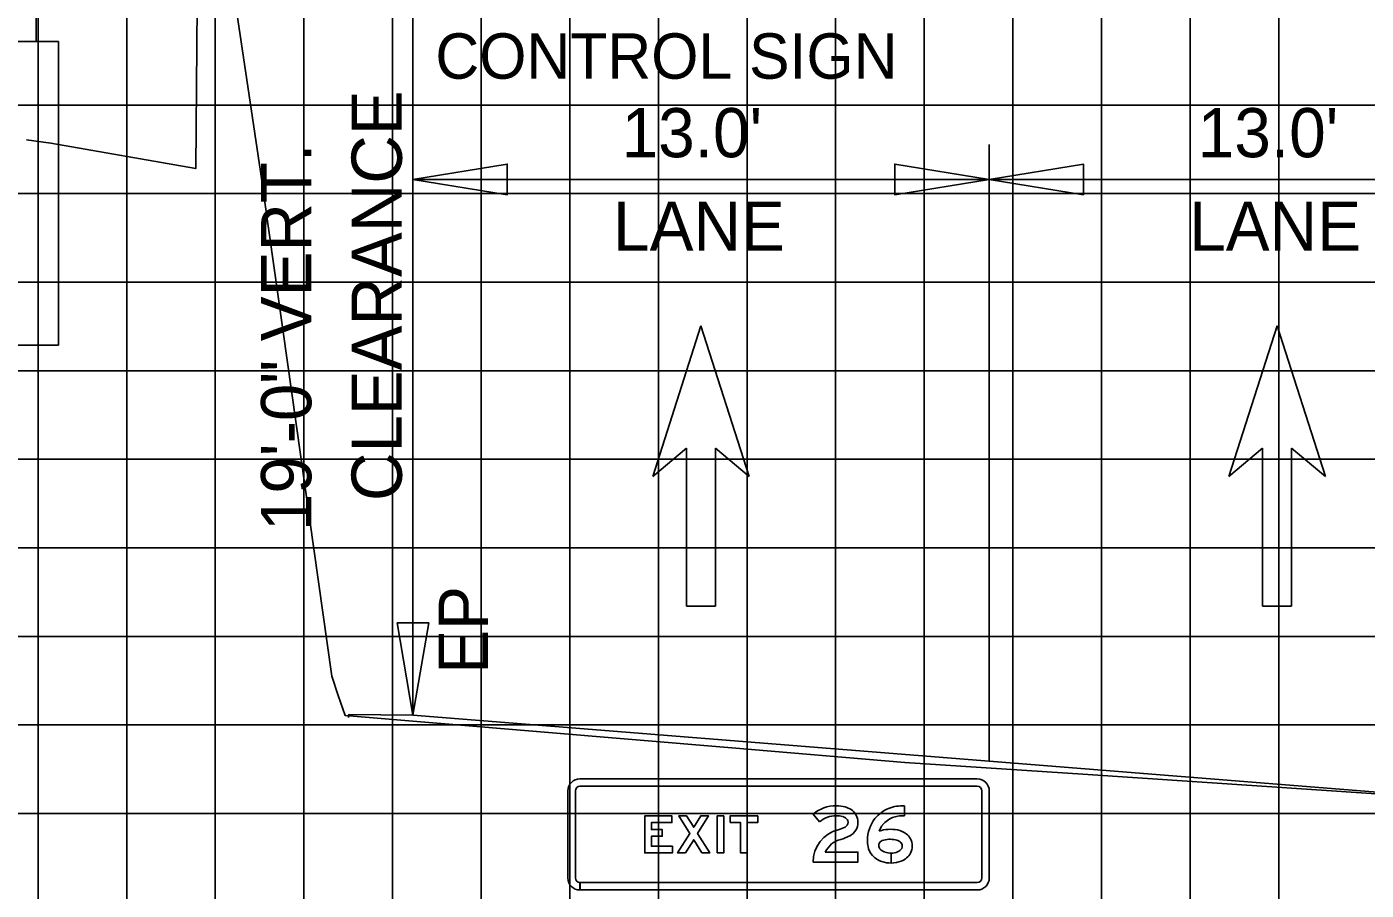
# Model space of a CAD drawing. Extents: x 2193008 to 2198143, y 1236112 to 1237864.
# Drawn here: x 2195346.38 to 2195376.61, y 1237268.37 to 1237287.87 of the extents above; entities that cross this region are included whole.
import ezdxf

# ---------------------------------------------------------------- set-up
doc = ezdxf.new("R2010")
doc.units = 0
for name, color, linetype in [('3', 7, 'Continuous'), ('CL-CNST', 7, 'Continuous'), ('GSBWFILL', 7, 'Continuous'), ('GSCOLORFILL', 7, 'Continuous'), ('GSDIMS', 7, 'Continuous'), ('GSOUTLINE', 7, 'Continuous'), ('Level 28', 7, 'Continuous'), ('Level 55', 7, 'Continuous'), ('Level 62', 7, 'Continuous'), ('M-ROADS', 7, 'Continuous'), ('V7Level1', 7, 'Continuous')]:
    doc.layers.add(name, color=color, linetype=linetype)

msp = doc.modelspace()

# ---------------------------------------------------------------- linework, layer by layer
at = {"layer": '3'}
for p, q in [((2195346.592, 1237301.295), (2195346.592, 1237287.538)), ((2195355.092, 1237272.327), (2195355.092, 1237291.42)), ((2195345.092, 1237287.538), (2195347.092, 1237287.538)), ((2195347.092, 1237280.686), (2195347.092, 1237287.538)), ((2195368.094, 1237271.287), (2195368.094, 1237285.215)), ((2195345.092, 1237280.686), (2195347.092, 1237280.686))]:
    msp.add_line(p, q, dxfattribs=at)
at = {"layer": 'CL-CNST'}
msp.add_lwpolyline([(2195353.64, 1237272.272), (2195353.643, 1237272.341), (2195355.092, 1237272.327), (2195368.094, 1237271.287), (2195381.096, 1237270.247), (2195387.382, 1237269.744)], dxfattribs=at)
at = {"layer": 'GSBWFILL'}
for points in [[(2195366.185, 1237270.282), (2195366.185, 1237270.057)], [(2195364.269, 1237269.918), (2195364.123, 1237270.09)], [(2195364.399, 1237269.235), (2195365.136, 1237269.235), (2195365.136, 1237269.01), (2195364.123, 1237269.01)], [(2195365.888, 1237269.213), (2195365.888, 1237268.988)], [(2195365.888, 1237268.988), (2195365.888, 1237269.213)]]:
    msp.add_lwpolyline(points, dxfattribs=at)
for points in [[(2195360.948, 1237269.368), (2195360.473, 1237269.368), (2195360.473, 1237269.592), (2195360.719, 1237269.592), (2195360.719, 1237269.742), (2195360.473, 1237269.742), (2195360.473, 1237269.901), (2195360.936, 1237269.901), (2195360.936, 1237270.051), (2195360.323, 1237270.051), (2195360.323, 1237269.218), (2195360.948, 1237269.218)], [(2195361.613, 1237269.218), (2195361.428, 1237269.514), (2195361.242, 1237269.218), (2195361.065, 1237269.218), (2195361.339, 1237269.655), (2195361.09, 1237270.051), (2195361.267, 1237270.051), (2195361.428, 1237269.796), (2195361.588, 1237270.051), (2195361.765, 1237270.051), (2195361.516, 1237269.655), (2195361.79, 1237269.218)], [(2195361.957, 1237269.218), (2195361.957, 1237270.051), (2195362.107, 1237270.051), (2195362.107, 1237269.218)], [(2195362.248, 1237269.901), (2195362.486, 1237269.901), (2195362.486, 1237269.218), (2195362.636, 1237269.218), (2195362.636, 1237269.901), (2195362.873, 1237269.901), (2195362.873, 1237270.051), (2195362.248, 1237270.051)]]:
    msp.add_lwpolyline(points, close=True, dxfattribs=at)
for centre, major_axis, start_param, end_param in [((2195364.645, 1237269.475), (0, 0.807), 0, 0.70376), ((2195364.645, 1237269.491), (0, 0.79), 6.02311, 6.283185), ((2195364.731, 1237269.812), (0, 0.458), 5.706931, 6.02311), ((2195366.102, 1237269.546), (0, 0.73), 0.134155, 0.638471), ((2195366.185, 1237268.93), (0, 1.352), 6.283185, 6.41734), ((2195364.645, 1237269.475), (0, 0.582), 0, 0.70376), ((2195364.645, 1237269.491), (0, 0.565), 6.02311, 6.283185), ((2195364.731, 1237269.812), (0, 0.233), 5.706931, 6.02311), ((2195364.794, 1237269.91), (0, 0.117), 4.712389, 5.706931), ((2195364.794, 1237269.91), (0, 0.342), 4.712389, 5.706931), ((2195366.146, 1237269.501), (0, 0.797), 0.905406, 1.570796), ((2195366.199, 1237269.415), (0, 0.893), 0.638464, 0.866813), ((2195366.199, 1237269.415), (0, 0.668), 0.638461, 0.860244), ((2195366.102, 1237269.546), (0, 0.505), 0.134155, 0.638471), ((2195366.185, 1237268.93), (0, 1.127), 0, 0.134155), ((2195364.878, 1237269.01), (0, 0.755), 0.25053, 1.570796), ((2195364.516, 1237270.423), (0, 0.704), 3.392123, 3.626327), ((2195364.787, 1237269.91), (0, 0.124), 3.626327, 4.712389), ((2195364.787, 1237269.91), (0, 0.349), 3.626327, 4.712389), ((2195366.146, 1237269.501), (0, 0.572), 0.912917, 1.195206), ((2195365.866, 1237268.921), (0, 0.829), 6.090019, 6.593179), ((2195365.932, 1237269.257), (0, 0.487), 5.634496, 6.090017), ((2195366.024, 1237269.378), (0, 0.335), 5.237857, 5.634492), ((2195364.878, 1237269.01), (0, 0.53), 0.25053, 1.132058), ((2195364.516, 1237270.423), (0, 0.929), 3.392123, 3.626327), ((2195366.014, 1237269.501), (0, 0.666), 1.570796, 1.784619), ((2195365.759, 1237269.431), (0, 0.402), 1.748918, 2.304124), ((2195365.723, 1237269.384), (0, 0.119), 0.35159, 2.216564), ((2195365.866, 1237268.921), (0, 0.604), 6.090019, 6.593179), ((2195365.932, 1237269.257), (0, 0.262), 5.6345, 6.090015), ((2195366.024, 1237269.378), (0, 0.11), 5.237857, 5.634492), ((2195366.009, 1237269.37), (0, 0.127), 4.712389, 5.237857), ((2195366.021, 1237269.37), (0, 0.115), 4.261086, 4.712389), ((2195366.009, 1237269.37), (0, 0.352), 4.712389, 5.237857), ((2195366.021, 1237269.37), (0, 0.34), 4.229443, 4.712389), ((2195365.831, 1237269.496), (0, 0.499), 2.304124, 2.823757), ((2195365.831, 1237269.496), (0, 0.274), 2.304124, 2.823757), ((2195365.888, 1237269.667), (0, 0.454), 2.823757, 3.141593), ((2195365.888, 1237269.603), (0, 0.39), 3.141673, 3.514879), ((2195365.888, 1237269.603), (0, 0.615), 3.141643, 3.514879), ((2195365.96, 1237269.418), (0, 0.192), 3.51487, 4.172439), ((2195365.96, 1237269.418), (0, 0.417), 3.514875, 4.194509), ((2195365.888, 1237269.667), (0, 0.679), 2.823757, 3.141593)]:
    msp.add_ellipse(centre, major_axis=major_axis, ratio=0.999994, start_param=start_param, end_param=end_param, dxfattribs=at)
at = {"layer": 'GSCOLORFILL'}
for p, q in [((2195367.828, 1237270.889), (2195358.861, 1237270.889)), ((2195358.59, 1237270.618), (2195358.59, 1237268.651)), ((2195358.757, 1237268.651), (2195358.757, 1237270.618)), ((2195358.861, 1237270.722), (2195367.828, 1237270.722)), ((2195367.932, 1237270.618), (2195367.932, 1237268.651)), ((2195368.098, 1237268.651), (2195368.098, 1237270.618)), ((2195358.861, 1237268.381), (2195358.861, 1237268.547)), ((2195367.828, 1237268.547), (2195358.863, 1237268.547)), ((2195358.863, 1237268.547), (2195358.863, 1237268.381)), ((2195358.863, 1237268.381), (2195367.828, 1237268.381))]:
    msp.add_line(p, q, dxfattribs=at)
for points in [[(2195366.185, 1237270.282), (2195366.185, 1237270.057)], [(2195364.269, 1237269.918), (2195364.123, 1237270.09)], [(2195364.399, 1237269.235), (2195365.136, 1237269.235), (2195365.136, 1237269.01), (2195364.123, 1237269.01)], [(2195365.888, 1237269.213), (2195365.888, 1237268.988)], [(2195365.888, 1237268.988), (2195365.888, 1237269.213)]]:
    msp.add_lwpolyline(points, dxfattribs=at)
for points in [[(2195360.948, 1237269.368), (2195360.473, 1237269.368), (2195360.473, 1237269.592), (2195360.719, 1237269.592), (2195360.719, 1237269.742), (2195360.473, 1237269.742), (2195360.473, 1237269.901), (2195360.936, 1237269.901), (2195360.936, 1237270.051), (2195360.323, 1237270.051), (2195360.323, 1237269.218), (2195360.948, 1237269.218)], [(2195361.613, 1237269.218), (2195361.428, 1237269.514), (2195361.242, 1237269.218), (2195361.065, 1237269.218), (2195361.339, 1237269.655), (2195361.09, 1237270.051), (2195361.267, 1237270.051), (2195361.428, 1237269.796), (2195361.588, 1237270.051), (2195361.765, 1237270.051), (2195361.516, 1237269.655), (2195361.79, 1237269.218)], [(2195361.957, 1237269.218), (2195361.957, 1237270.051), (2195362.107, 1237270.051), (2195362.107, 1237269.218)], [(2195362.248, 1237269.901), (2195362.486, 1237269.901), (2195362.486, 1237269.218), (2195362.636, 1237269.218), (2195362.636, 1237269.901), (2195362.873, 1237269.901), (2195362.873, 1237270.051), (2195362.248, 1237270.051)]]:
    msp.add_lwpolyline(points, close=True, dxfattribs=at)
for centre, radius, start, end in [((2195358.861, 1237270.618), 0.271, 90, 180), ((2195367.828, 1237270.618), 0.271, 0, 90), ((2195358.861, 1237270.618), 0.104, 90, 180), ((2195367.828, 1237270.618), 0.104, 0, 90), ((2195358.861, 1237268.651), 0.271, 180, 270), ((2195358.861, 1237268.651), 0.104, 180, 270), ((2195367.828, 1237268.651), 0.271, 270, 0), ((2195367.828, 1237268.651), 0.104, 270, 0)]:
    msp.add_arc(centre, radius, start, end, dxfattribs=at)
for centre, major_axis, start_param, end_param in [((2195364.645, 1237269.475), (0, 0.807), 0, 0.70376), ((2195364.645, 1237269.491), (0, 0.79), 6.02311, 6.283185), ((2195364.731, 1237269.812), (0, 0.458), 5.706931, 6.02311), ((2195366.102, 1237269.546), (0, 0.73), 0.134155, 0.638471), ((2195366.185, 1237268.93), (0, 1.352), 6.283185, 6.41734), ((2195364.645, 1237269.475), (0, 0.582), 0, 0.70376), ((2195364.645, 1237269.491), (0, 0.565), 6.02311, 6.283185), ((2195364.731, 1237269.812), (0, 0.233), 5.706931, 6.02311), ((2195364.794, 1237269.91), (0, 0.117), 4.712389, 5.706931), ((2195364.794, 1237269.91), (0, 0.342), 4.712389, 5.706931), ((2195366.146, 1237269.501), (0, 0.797), 0.905406, 1.570796), ((2195366.199, 1237269.415), (0, 0.893), 0.638464, 0.866813), ((2195366.199, 1237269.415), (0, 0.668), 0.638461, 0.860244), ((2195366.102, 1237269.546), (0, 0.505), 0.134155, 0.638471), ((2195366.185, 1237268.93), (0, 1.127), 0, 0.134155), ((2195364.878, 1237269.01), (0, 0.755), 0.25053, 1.570796), ((2195364.516, 1237270.423), (0, 0.704), 3.392123, 3.626327), ((2195364.787, 1237269.91), (0, 0.124), 3.626327, 4.712389), ((2195364.787, 1237269.91), (0, 0.349), 3.626327, 4.712389), ((2195366.146, 1237269.501), (0, 0.572), 0.912917, 1.195206), ((2195365.866, 1237268.921), (0, 0.829), 6.090019, 6.593179), ((2195365.932, 1237269.257), (0, 0.487), 5.634496, 6.090017), ((2195366.024, 1237269.378), (0, 0.335), 5.237857, 5.634492), ((2195364.878, 1237269.01), (0, 0.53), 0.25053, 1.132058), ((2195364.516, 1237270.423), (0, 0.929), 3.392123, 3.626327), ((2195366.014, 1237269.501), (0, 0.666), 1.570796, 1.784619), ((2195365.759, 1237269.431), (0, 0.402), 1.748918, 2.304124), ((2195365.723, 1237269.384), (0, 0.119), 0.35159, 2.216564), ((2195365.866, 1237268.921), (0, 0.604), 6.090019, 6.593179), ((2195365.932, 1237269.257), (0, 0.262), 5.6345, 6.090015), ((2195366.024, 1237269.378), (0, 0.11), 5.237857, 5.634492), ((2195366.009, 1237269.37), (0, 0.127), 4.712389, 5.237857), ((2195366.021, 1237269.37), (0, 0.115), 4.261086, 4.712389), ((2195366.009, 1237269.37), (0, 0.352), 4.712389, 5.237857), ((2195366.021, 1237269.37), (0, 0.34), 4.229443, 4.712389), ((2195365.831, 1237269.496), (0, 0.499), 2.304124, 2.823757), ((2195365.831, 1237269.496), (0, 0.274), 2.304124, 2.823757), ((2195365.888, 1237269.667), (0, 0.454), 2.823757, 3.141593), ((2195365.888, 1237269.603), (0, 0.39), 3.141673, 3.514879), ((2195365.888, 1237269.603), (0, 0.615), 3.141643, 3.514879), ((2195365.96, 1237269.418), (0, 0.192), 3.51487, 4.172439), ((2195365.96, 1237269.418), (0, 0.417), 3.514875, 4.194509), ((2195365.888, 1237269.667), (0, 0.679), 2.823757, 3.141593)]:
    msp.add_ellipse(centre, major_axis=major_axis, ratio=0.999994, start_param=start_param, end_param=end_param, dxfattribs=at)
at = {"layer": 'GSDIMS'}
for p, q in [((2195355.092, 1237284.427), (2195368.094, 1237284.427)), ((2195368.094, 1237284.427), (2195381.097, 1237284.427))]:
    msp.add_line(p, q, dxfattribs=at)
for points in [[(2195355.092, 1237284.427), (2195357.22, 1237284.079), (2195357.22, 1237284.774)], [(2195368.094, 1237284.427), (2195365.966, 1237284.079), (2195365.966, 1237284.774)], [(2195368.094, 1237284.427), (2195370.223, 1237284.079), (2195370.223, 1237284.774)], [(2195355.092, 1237272.327), (2195354.737, 1237274.41), (2195355.447, 1237274.41)]]:
    msp.add_lwpolyline(points, close=True, dxfattribs=at)
at = {"layer": 'GSOUTLINE'}
for points in [[(2195366.185, 1237270.282), (2195366.185, 1237270.057)], [(2195364.269, 1237269.918), (2195364.123, 1237270.09)], [(2195364.399, 1237269.235), (2195365.136, 1237269.235), (2195365.136, 1237269.01), (2195364.123, 1237269.01)]]:
    msp.add_lwpolyline(points, dxfattribs=at)
for points in [[(2195360.948, 1237269.368), (2195360.473, 1237269.368), (2195360.473, 1237269.592), (2195360.719, 1237269.592), (2195360.719, 1237269.742), (2195360.473, 1237269.742), (2195360.473, 1237269.901), (2195360.936, 1237269.901), (2195360.936, 1237270.051), (2195360.323, 1237270.051), (2195360.323, 1237269.218), (2195360.948, 1237269.218)], [(2195361.613, 1237269.218), (2195361.428, 1237269.514), (2195361.242, 1237269.218), (2195361.065, 1237269.218), (2195361.339, 1237269.655), (2195361.09, 1237270.051), (2195361.267, 1237270.051), (2195361.428, 1237269.796), (2195361.588, 1237270.051), (2195361.765, 1237270.051), (2195361.516, 1237269.655), (2195361.79, 1237269.218)], [(2195361.957, 1237269.218), (2195361.957, 1237270.051), (2195362.107, 1237270.051), (2195362.107, 1237269.218)], [(2195362.248, 1237269.901), (2195362.486, 1237269.901), (2195362.486, 1237269.218), (2195362.636, 1237269.218), (2195362.636, 1237269.901), (2195362.873, 1237269.901), (2195362.873, 1237270.051), (2195362.248, 1237270.051)]]:
    msp.add_lwpolyline(points, close=True, dxfattribs=at)
for centre, major_axis, start_param, end_param in [((2195364.645, 1237269.475), (0, 0.807), 0, 0.70376), ((2195364.645, 1237269.491), (0, 0.79), 6.02311, 6.283185), ((2195364.731, 1237269.812), (0, 0.458), 5.706931, 6.02311), ((2195366.102, 1237269.546), (0, 0.73), 0.134155, 0.638471), ((2195366.185, 1237268.93), (0, 1.352), 6.283185, 6.41734), ((2195364.645, 1237269.475), (0, 0.582), 0, 0.70376), ((2195364.645, 1237269.491), (0, 0.565), 6.02311, 6.283185), ((2195364.731, 1237269.812), (0, 0.233), 5.706931, 6.02311), ((2195364.794, 1237269.91), (0, 0.117), 4.712389, 5.706931), ((2195364.794, 1237269.91), (0, 0.342), 4.712389, 5.706931), ((2195366.146, 1237269.501), (0, 0.797), 0.905406, 1.570796), ((2195366.199, 1237269.415), (0, 0.893), 0.638464, 0.866813), ((2195366.199, 1237269.415), (0, 0.668), 0.638461, 0.860244), ((2195366.102, 1237269.546), (0, 0.505), 0.134155, 0.638471), ((2195366.185, 1237268.93), (0, 1.127), 0, 0.134155), ((2195364.878, 1237269.01), (0, 0.755), 0.25053, 1.570796), ((2195364.516, 1237270.423), (0, 0.704), 3.392123, 3.626327), ((2195364.787, 1237269.91), (0, 0.124), 3.626327, 4.712389), ((2195364.787, 1237269.91), (0, 0.349), 3.626327, 4.712389), ((2195366.146, 1237269.501), (0, 0.572), 0.912917, 1.195206), ((2195365.866, 1237268.921), (0, 0.829), 6.090019, 6.593179), ((2195365.932, 1237269.257), (0, 0.487), 5.634496, 6.090017), ((2195366.024, 1237269.378), (0, 0.335), 5.237857, 5.634492), ((2195364.878, 1237269.01), (0, 0.53), 0.25053, 1.132058), ((2195364.516, 1237270.423), (0, 0.929), 3.392123, 3.626327), ((2195366.014, 1237269.501), (0, 0.666), 1.570796, 1.784619), ((2195365.759, 1237269.431), (0, 0.402), 1.748918, 2.304124), ((2195365.723, 1237269.384), (0, 0.119), 0.35159, 2.216564), ((2195365.866, 1237268.921), (0, 0.604), 6.090019, 6.593179), ((2195365.932, 1237269.257), (0, 0.262), 5.6345, 6.090015), ((2195366.024, 1237269.378), (0, 0.11), 5.237857, 5.634492), ((2195366.009, 1237269.37), (0, 0.127), 4.712389, 5.237857), ((2195366.021, 1237269.37), (0, 0.115), 4.261086, 4.712389), ((2195366.009, 1237269.37), (0, 0.352), 4.712389, 5.237857), ((2195366.021, 1237269.37), (0, 0.34), 4.229443, 4.712389), ((2195365.831, 1237269.496), (0, 0.499), 2.304124, 2.823757), ((2195365.831, 1237269.496), (0, 0.274), 2.304124, 2.823757), ((2195365.888, 1237269.667), (0, 0.454), 2.823757, 3.141593), ((2195365.888, 1237269.603), (0, 0.39), 3.141593, 3.514879), ((2195365.888, 1237269.603), (0, 0.615), 3.141593, 3.514879), ((2195365.96, 1237269.418), (0, 0.192), 3.51487, 4.172439), ((2195365.96, 1237269.418), (0, 0.417), 3.514875, 4.194509), ((2195365.888, 1237269.667), (0, 0.679), 2.823757, 3.141593)]:
    msp.add_ellipse(centre, major_axis=major_axis, ratio=0.999994, start_param=start_param, end_param=end_param, dxfattribs=at)
at = {"layer": 'Level 28'}
for p, q in [((2195361.593, 1237281.117), (2195360.504, 1237277.719)), ((2195362.682, 1237277.719), (2195361.593, 1237281.117)), ((2195374.595, 1237281.117), (2195373.506, 1237277.719)), ((2195375.685, 1237277.719), (2195374.595, 1237281.117)), ((2195360.504, 1237277.719), (2195361.266, 1237278.359)), ((2195361.266, 1237278.359), (2195361.266, 1237274.787)), ((2195361.92, 1237274.787), (2195361.92, 1237278.359)), ((2195361.92, 1237278.359), (2195362.682, 1237277.719)), ((2195373.506, 1237277.719), (2195374.269, 1237278.359)), ((2195374.269, 1237278.359), (2195374.269, 1237274.787)), ((2195374.922, 1237274.787), (2195374.922, 1237278.359)), ((2195374.922, 1237278.359), (2195375.685, 1237277.719)), ((2195361.266, 1237274.787), (2195361.92, 1237274.787)), ((2195374.269, 1237274.787), (2195374.922, 1237274.787))]:
    msp.add_line(p, q, dxfattribs=at)
at = {"layer": 'Level 62'}
for p, q in [((2195346.632, 1237258.106), (2195346.632, 1237318.106)), ((2195348.632, 1237258.106), (2195348.632, 1237318.106)), ((2195350.632, 1237258.106), (2195350.632, 1237318.106)), ((2195352.632, 1237258.106), (2195352.632, 1237318.106)), ((2195354.632, 1237258.106), (2195354.632, 1237318.106)), ((2195356.632, 1237258.106), (2195356.632, 1237318.106)), ((2195358.632, 1237258.106), (2195358.632, 1237318.106)), ((2195360.632, 1237258.106), (2195360.632, 1237318.106)), ((2195362.632, 1237258.106), (2195362.632, 1237318.106)), ((2195364.632, 1237258.106), (2195364.632, 1237318.106)), ((2195366.632, 1237258.106), (2195366.632, 1237318.106)), ((2195368.632, 1237258.106), (2195368.632, 1237318.106)), ((2195370.632, 1237258.106), (2195370.632, 1237318.106)), ((2195372.632, 1237258.106), (2195372.632, 1237318.106)), ((2195374.632, 1237258.106), (2195374.632, 1237318.106)), ((2195328.632, 1237286.106), (2195448.632, 1237286.106)), ((2195328.632, 1237284.106), (2195448.632, 1237284.106)), ((2195328.632, 1237282.106), (2195448.632, 1237282.106)), ((2195328.632, 1237280.106), (2195448.632, 1237280.106)), ((2195328.632, 1237278.106), (2195448.632, 1237278.106)), ((2195328.632, 1237276.106), (2195448.632, 1237276.106)), ((2195328.632, 1237274.106), (2195448.632, 1237274.106)), ((2195328.632, 1237272.106), (2195448.632, 1237272.106)), ((2195328.632, 1237270.106), (2195448.632, 1237270.106))]:
    msp.add_line(p, q, dxfattribs=at)
at = {"layer": 'M-ROADS'}
msp.add_lwpolyline([(2195346.372, 1237285.319), (2195346.923, 1237285.247), (2195350.191, 1237284.671), (2195350.266, 1237293.904), (2195351.655, 1237284.607), (2195353.263, 1237273.21), (2195353.402, 1237272.769), (2195353.563, 1237272.32), (2195362.292, 1237271.588), (2195366.19, 1237271.258), (2195370.209, 1237270.993), (2195379.415, 1237270.375)], dxfattribs=at)
at = {"layer": 'V7Level1'}
msp.add_lwpolyline([(2195347.092, 1237280.686), (2195345.092, 1237280.686), (2195345.092, 1237287.538), (2195347.092, 1237287.538)], close=True, dxfattribs=at)

# ---------------------------------------------------------------- texts
at = {"layer": 'Level 55'}
for s, height, p in [('CONTROL SIGN', 1.02464, (2195355.598, 1237286.701)), ("13.0'", 1.1105, (2195359.8, 1237284.927)), ("13.0'", 1.1105, (2195372.803, 1237284.927)), ('LANE', 1.1105, (2195359.608, 1237282.816)), ('LANE', 1.1105, (2195372.61, 1237282.816))]:
    msp.add_text(s, height=height, dxfattribs=at).set_placement(p)
for s, height, p in [('CLEARANCE', 1.1346, (2195354.841, 1237277.163)), ('19\'-0" VERT.', 1.13464, (2195352.798, 1237276.486)), ('EP', 1.1105, (2195356.784, 1237273.262))]:
    msp.add_text(s, height=height, rotation=90, dxfattribs=at).set_placement(p)

doc.saveas('drawing.dxf')
